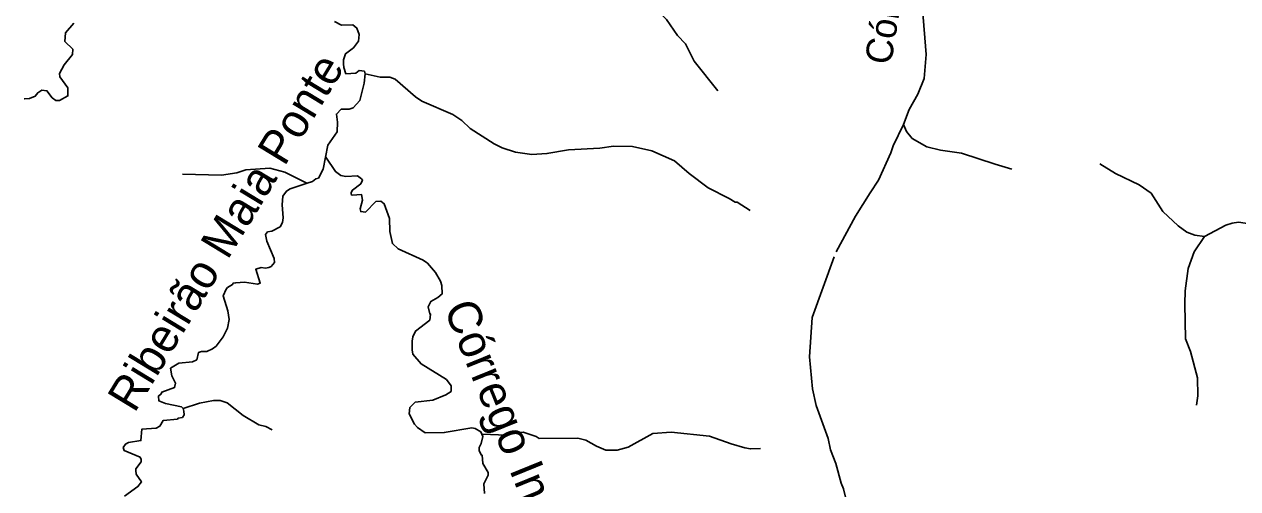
# Model space of a CAD drawing. Extents: x 393 to 446.6, y 8175.5 to 8231.
# Drawn here: x 393.16 to 400.42, y 8194.39 to 8197.16 of the extents above; entities that cross this region are included whole.
import ezdxf
from ezdxf.enums import TextEntityAlignment as Align

# ---------------------------------------------------------------- set-up
doc = ezdxf.new("R2010")
doc.units = 0
doc.header["$LTSCALE"] = 0.064
doc.linetypes.add('LONG_DASHED', pattern=[7.5, 6, -1.5])
doc.layers.add('61', color=7, linetype='Continuous')
doc.layers.add('7', color=7, linetype='Continuous', lineweight=25)
doc.layers.add('9', color=7, linetype='LONG_DASHED', lineweight=25)

msp = doc.modelspace()

# ---------------------------------------------------------------- linework, layer by layer
at = {"layer": '7'}
for points in [[(397.3093, 8196.7665), (397.1689, 8196.9446), (397.1173, 8197.0479), (397.0688, 8197.098), (397.0042, 8197.1933), (396.9364, 8197.2611), (396.8767, 8197.2982), (396.7734, 8197.3369), (396.599, 8197.3709), (396.2437, 8197.3725), (396.1307, 8197.3595), (396.0532, 8197.3676), (395.9369, 8197.4161), (395.8658, 8197.4661), (395.8577, 8197.4904), (395.8564, 8197.5401)], [(393.1649, 8196.7188), (393.1658, 8196.7189), (393.196, 8196.7212), (393.2305, 8196.7346), (393.245, 8196.7556), (393.2692, 8196.7701), (393.2999, 8196.7669), (393.3322, 8196.725), (393.3532, 8196.7088), (393.3758, 8196.7088), (393.4258, 8196.7363), (393.4258, 8196.7847), (393.3774, 8196.8509), (393.3758, 8196.8703), (393.4033, 8196.922), (393.4533, 8196.9833), (393.4549, 8197.0156), (393.4081, 8197.0608), (393.4113, 8197.1125), (393.4614, 8197.1707)], [(395.2027, 8196.8686), (395.1981, 8196.8838), (395.1666, 8196.8884), (395.1456, 8196.8719), (395.0875, 8196.8686), (395.0745, 8196.9058), (395.0729, 8196.9284), (395.0729, 8196.951), (395.0843, 8196.9882), (395.1327, 8197.0237), (395.1617, 8197.0641), (395.1666, 8197.1028), (395.1521, 8197.1416), (395.1295, 8197.1609), (395.0617, 8197.1593), (395.0196, 8197.1803)], [(394.9657, 8196.3712), (394.9793, 8196.4424), (395.0342, 8196.5215), (395.0374, 8196.5796), (395.031, 8196.6281), (395.0584, 8196.6571), (395.1069, 8196.6571), (395.1311, 8196.6652), (395.1699, 8196.7088), (395.1957, 8196.8122), (395.2027, 8196.8686)], [(397.5034, 8196.0512), (397.4257, 8196.1016), (397.4128, 8196.1016), (397.3789, 8196.1242), (397.2529, 8196.1872), (397.1383, 8196.2728), (397.0511, 8196.3487), (396.9155, 8196.4084), (396.7992, 8196.4343), (396.6862, 8196.4359), (396.6054, 8196.4246), (396.4181, 8196.4149), (396.2889, 8196.3923), (396.1985, 8196.3858), (396.1016, 8196.4004), (396.0209, 8196.4262), (395.9724, 8196.4504), (395.8303, 8196.5409), (395.7802, 8196.5893), (395.727, 8196.6248), (395.5412, 8196.7056), (395.5025, 8196.7314), (395.3814, 8196.8363), (395.3491, 8196.8477), (395.2926, 8196.8477), (395.2027, 8196.8686)], [(394.8548, 8196.2144), (394.8875, 8196.2254), (394.9083, 8196.2421), (394.9228, 8196.2453), (394.9518, 8196.2986), (394.9657, 8196.3712)], [(395.8992, 8194.7168), (395.8942, 8194.7305), (395.8605, 8194.7503), (395.84, 8194.7533), (395.6753, 8194.7258), (395.5606, 8194.7242), (395.5154, 8194.7549), (395.4976, 8194.7759), (395.4653, 8194.8372), (395.4702, 8194.8744), (395.5009, 8194.9067), (395.6075, 8194.9196), (395.685, 8194.9519), (395.7156, 8194.9713), (395.7172, 8195.0052), (395.6882, 8195.0423), (395.5364, 8195.136), (395.4879, 8195.1941), (395.4831, 8195.22), (395.4831, 8195.2717), (395.488, 8195.2975), (395.5041, 8195.3314), (395.5881, 8195.3976), (395.5929, 8195.4331), (395.5881, 8195.4347), (395.5784, 8195.4767), (395.5945, 8195.509), (395.6365, 8195.5316), (395.6624, 8195.5542), (395.6607, 8195.6043), (395.6526, 8195.6301), (395.6236, 8195.6818), (395.5752, 8195.7367), (395.5493, 8195.7545), (395.3991, 8195.8239), (395.3652, 8195.8546), (395.3507, 8195.9273), (395.3475, 8196.0048), (395.3168, 8196.0919), (395.2958, 8196.1081), (395.2667, 8196.1065), (395.2038, 8196.0419), (395.1763, 8196.0451), (395.1731, 8196.0629), (395.186, 8196.1146), (395.1811, 8196.1468), (395.1251, 8196.1433), (395.1181, 8196.1479), (395.1181, 8196.1596), (395.1262, 8196.1735), (395.1763, 8196.2114), (395.186, 8196.234), (395.1811, 8196.2405), (395.1569, 8196.2599), (395.0875, 8196.255), (395.0568, 8196.2615), (395.0245, 8196.2841), (394.9668, 8196.3696), (394.9657, 8196.3712)], [(399.5932, 8196.3311), (399.6864, 8196.2728), (399.8285, 8196.205), (399.8996, 8196.1565), (399.9706, 8196.0468), (400.061, 8195.9595), (400.1143, 8195.9224), (400.1612, 8195.9046), (400.2193, 8195.896)], [(394.1102, 8196.2695), (394.3447, 8196.2631), (394.4351, 8196.2776), (394.49, 8196.2954), (394.6321, 8196.3051), (394.7226, 8196.2809), (394.8537, 8196.2149), (394.8548, 8196.2144)], [(394.1143, 8194.8702), (394.1038, 8194.8795), (394.0088, 8194.9002), (393.97, 8194.9147), (393.9668, 8194.9438), (393.983, 8194.9568), (393.9862, 8194.9664), (394.0637, 8194.9939), (394.0685, 8195.0213), (394.0459, 8195.065), (394.0395, 8195.1101), (394.0896, 8195.1408), (394.1703, 8195.1489), (394.1961, 8195.1602), (394.2058, 8195.2038), (394.2236, 8195.2103), (394.2559, 8195.2103), (394.2898, 8195.2264), (394.3124, 8195.2425), (394.3527, 8195.2975), (394.3802, 8195.3492), (394.3899, 8195.4008), (394.3818, 8195.4525), (394.3543, 8195.5429), (394.3721, 8195.5817), (394.3802, 8195.593), (394.4093, 8195.6091), (394.4125, 8195.6172), (394.4287, 8195.6204), (394.4803, 8195.6236), (394.5579, 8195.6124), (394.5756, 8195.6188), (394.5482, 8195.7012), (394.5805, 8195.7125), (394.6063, 8195.7076), (394.6273, 8195.7108), (394.6402, 8195.7173), (394.6612, 8195.7415), (394.6579, 8195.7658), (394.6143, 8195.8691), (394.6063, 8195.9079), (394.6192, 8195.924), (394.6451, 8195.9289), (394.6935, 8195.9547), (394.708, 8195.9805), (394.7128, 8196.008), (394.7064, 8196.0855), (394.7096, 8196.1372), (394.7322, 8196.1678), (394.7548, 8196.1807), (394.8548, 8196.2144)], [(400.2193, 8195.896), (400.3469, 8195.9644), (400.384, 8195.9773), (400.4228, 8195.9821), (400.5391, 8195.9644), (400.6295, 8195.9595), (400.6715, 8195.9595), (400.7328, 8195.9708), (400.8006, 8196.0096), (400.8586, 8196.0878)], [(400.1707, 8194.8896), (400.18, 8194.9443), (400.1773, 8195.052), (400.1353, 8195.2103), (400.1063, 8195.2846), (400.1014, 8195.4945), (400.103, 8195.572), (400.1208, 8195.706), (400.1563, 8195.8045), (400.2193, 8195.896)], [(394.6462, 8194.7413), (394.609, 8194.7622), (394.5659, 8194.771), (394.4739, 8194.8275), (394.377, 8194.9035), (394.335, 8194.9164), (394.2963, 8194.918), (394.2123, 8194.9018), (394.1143, 8194.8702)], [(393.7638, 8194.3464), (393.8441, 8194.4029), (393.8651, 8194.4319), (393.8328, 8194.4772), (393.8312, 8194.4998), (393.8312, 8194.5095), (393.8635, 8194.5515), (393.8635, 8194.5644), (393.857, 8194.5789), (393.7617, 8194.6192), (393.7569, 8194.637), (393.7698, 8194.6564), (393.7876, 8194.6661), (393.8619, 8194.6774), (393.8683, 8194.7468), (393.9539, 8194.7517), (393.9749, 8194.7646), (393.9959, 8194.7985), (394.0798, 8194.805), (394.0847, 8194.8114), (394.1105, 8194.8162), (394.1202, 8194.8324), (394.119, 8194.8528), (394.1143, 8194.8702)], [(395.9159, 8194.3625), (395.9126, 8194.419), (395.9368, 8194.4707), (395.9368, 8194.4868), (395.9062, 8194.5401), (395.9013, 8194.5902), (395.8949, 8194.5918), (395.8836, 8194.6193), (395.8836, 8194.637), (395.8965, 8194.6613), (395.9047, 8194.7014), (395.8992, 8194.7168)], [(397.5645, 8194.6304), (397.5051, 8194.6281), (397.4709, 8194.6354), (397.3902, 8194.658), (397.261, 8194.7048), (397.0317, 8194.7274), (396.9219, 8194.721), (396.7734, 8194.6386), (396.7088, 8194.6208), (396.6409, 8194.6208), (396.5844, 8194.6435), (396.5214, 8194.6806), (396.473, 8194.6919), (396.2421, 8194.6903), (396.2243, 8194.7016), (396.1468, 8194.7274), (396.1064, 8194.7258), (396.0499, 8194.7097), (395.9024, 8194.7166), (395.8992, 8194.7168)]]:
    msp.add_lwpolyline(points, dxfattribs=at)
at = {"layer": '9'}
for points in [[(398.4195, 8196.5647), (398.4545, 8196.6546), (398.506, 8196.7459), (398.5431, 8196.8412), (398.5561, 8196.9833), (398.5335, 8197.2562), (398.5108, 8197.4387), (398.5141, 8197.6276), (398.5292, 8197.6755), (398.5431, 8197.7197), (398.5884, 8197.9264), (398.6142, 8197.9958), (398.7094, 8198.2009), (398.7777, 8198.4182)], [(398.1378, 8194.1043), (398.091, 8194.2656), (398.0619, 8194.39), (398.0474, 8194.4239), (398.0151, 8194.5418), (397.9828, 8194.6225), (397.9699, 8194.6903), (397.8988, 8194.8873), (397.8762, 8194.9875), (397.8585, 8195.178), (397.8746, 8195.4138), (398.0167, 8195.8061), (398.133, 8196.0177), (398.2212, 8196.1567), (398.2702, 8196.2341), (398.3445, 8196.3972), (398.3575, 8196.4375), (398.4195, 8196.5647)], [(399.0671, 8196.298), (398.9677, 8196.3297), (398.766, 8196.3939), (398.6401, 8196.4117), (398.5593, 8196.4326), (398.4721, 8196.4827), (398.4382, 8196.5247), (398.4195, 8196.5647)]]:
    msp.add_lwpolyline(points, dxfattribs=at)

# ---------------------------------------------------------------- texts
at = {"layer": '61'}
for s, height, rotation, p in [('Córrego Estaleiro', 0.16, 80.87, (398.477, 8197.7388)), ('Ribeirão Maia Ponte', 0.2, 58.691, (394.4533, 8195.8723)), ('Córrego Indaiá', 0.2, 292.094, (396.0029, 8194.6493))]:
    msp.add_text(s, height=height, rotation=rotation, dxfattribs=at).set_placement(p, align=Align.CENTER)

doc.saveas('drawing.dxf')
